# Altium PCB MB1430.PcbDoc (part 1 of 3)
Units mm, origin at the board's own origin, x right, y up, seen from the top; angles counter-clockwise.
Board outline 18.54 x 50.29 mm, 4 copper layers (Top Layer, Signal Layer 1, Signal Layer 2, Bottom Layer), stack 1.614 mm thick; 124 components, 85 nets, 561 pads, 241 vias.
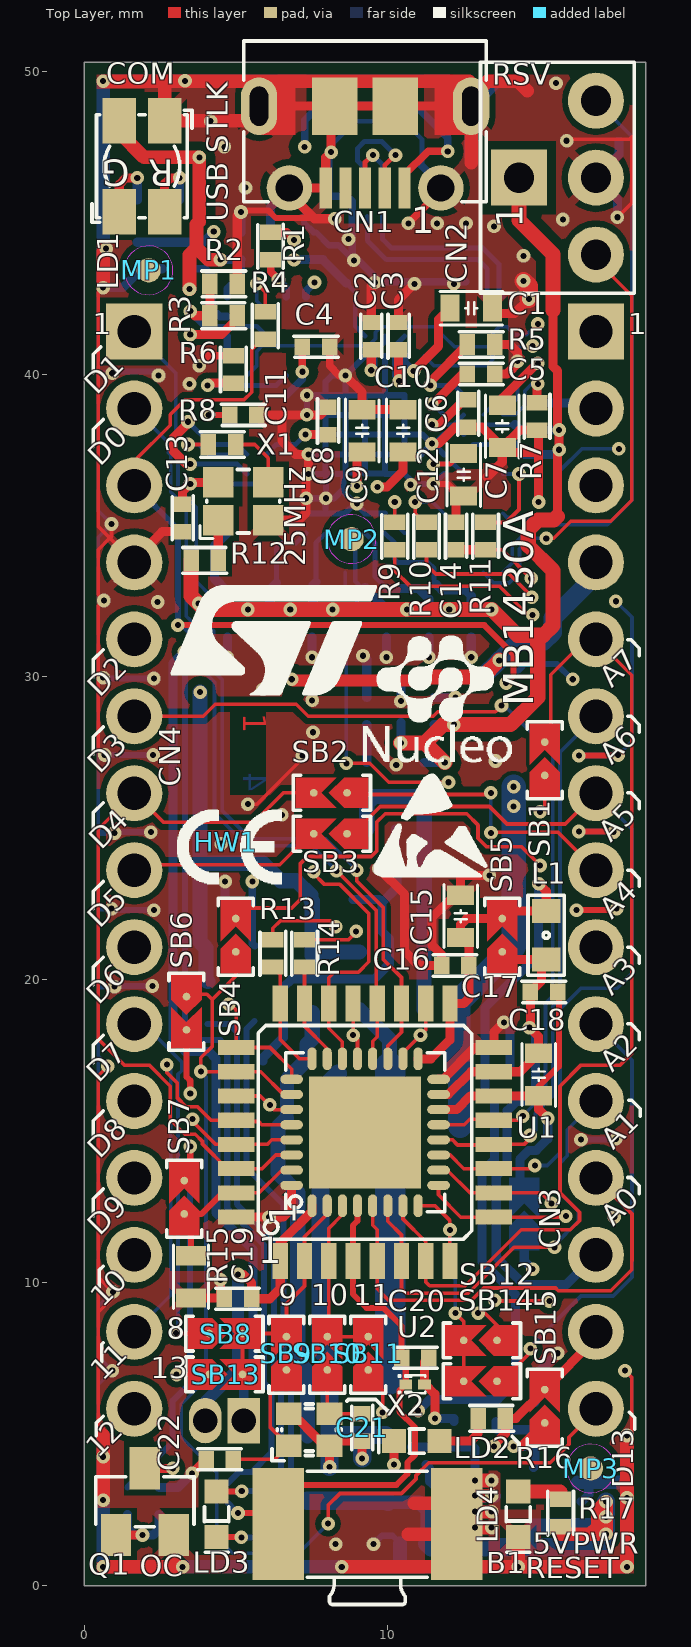
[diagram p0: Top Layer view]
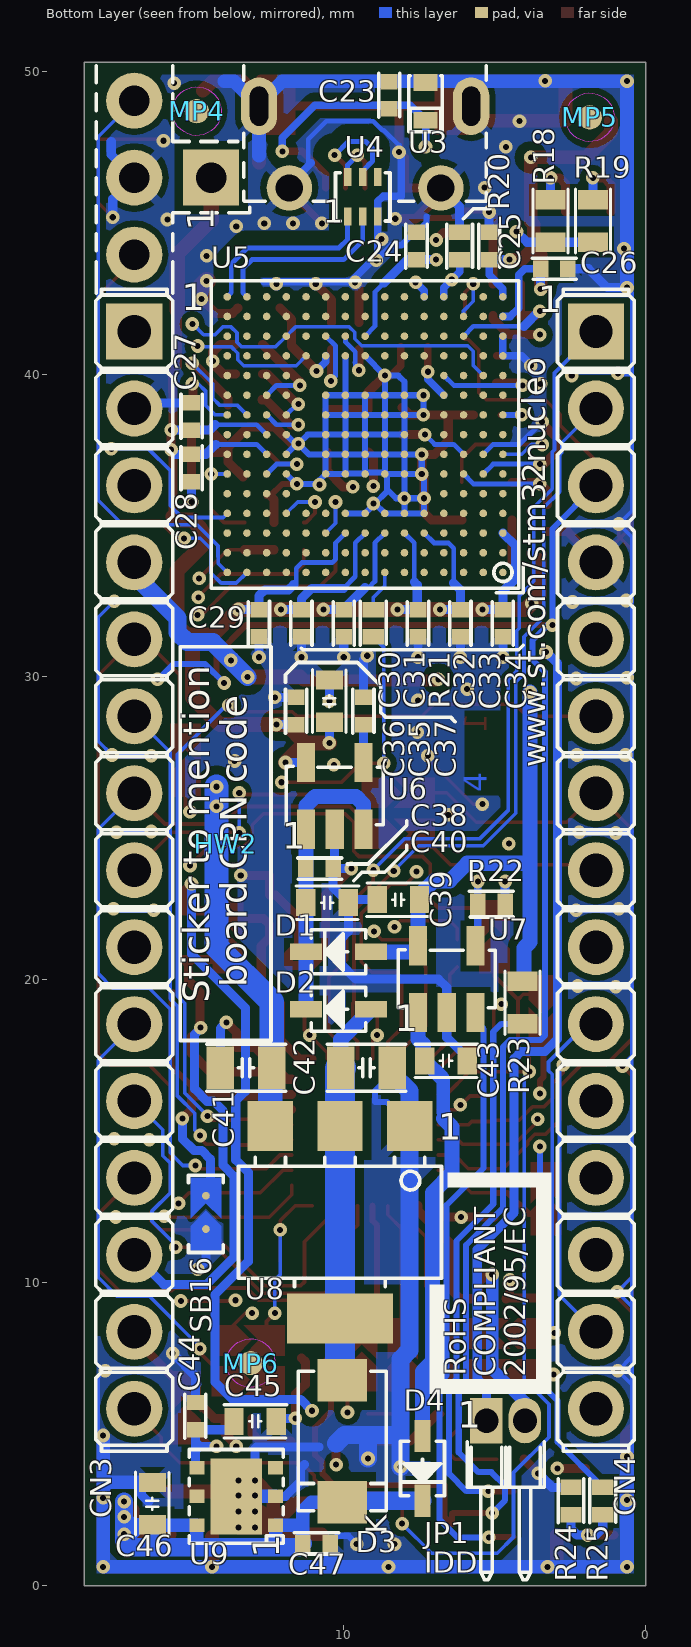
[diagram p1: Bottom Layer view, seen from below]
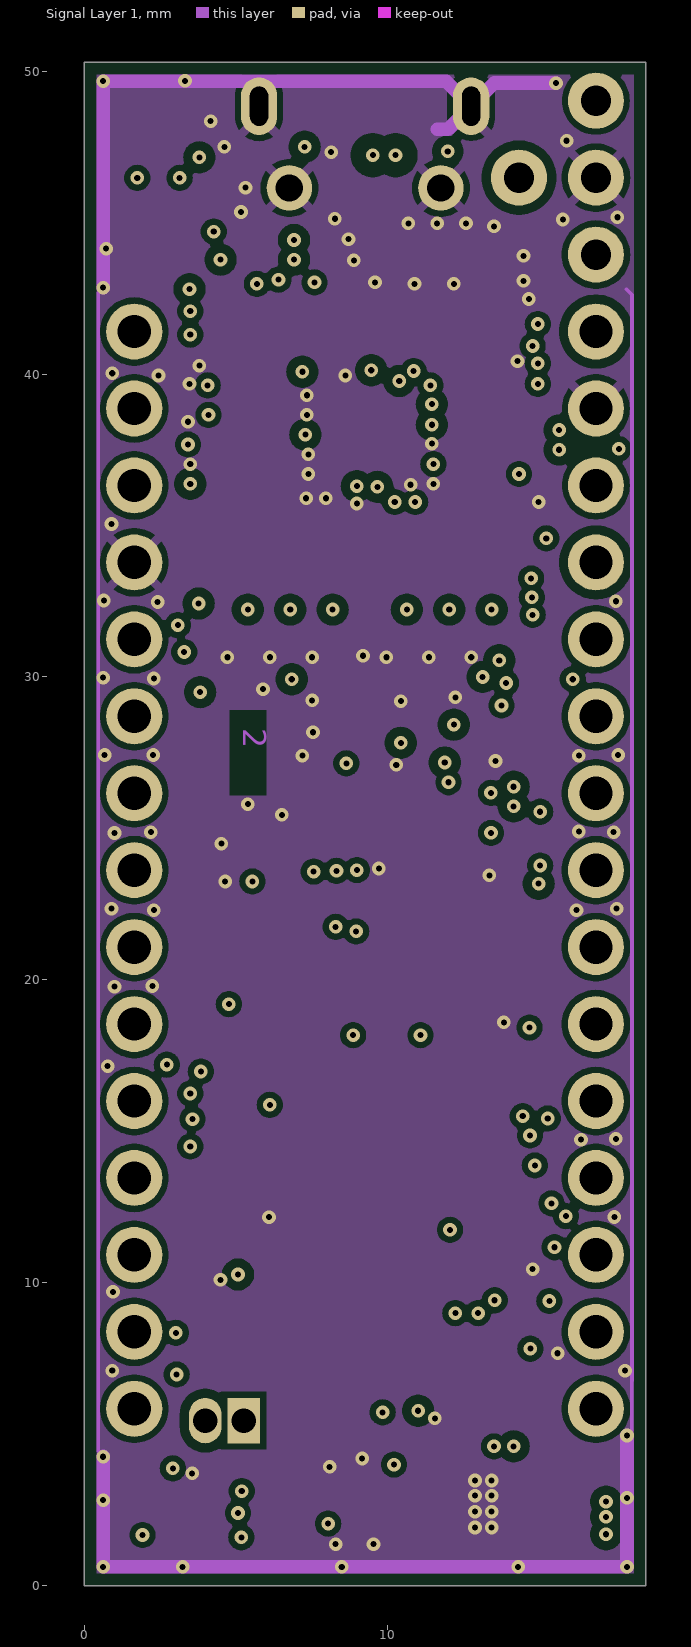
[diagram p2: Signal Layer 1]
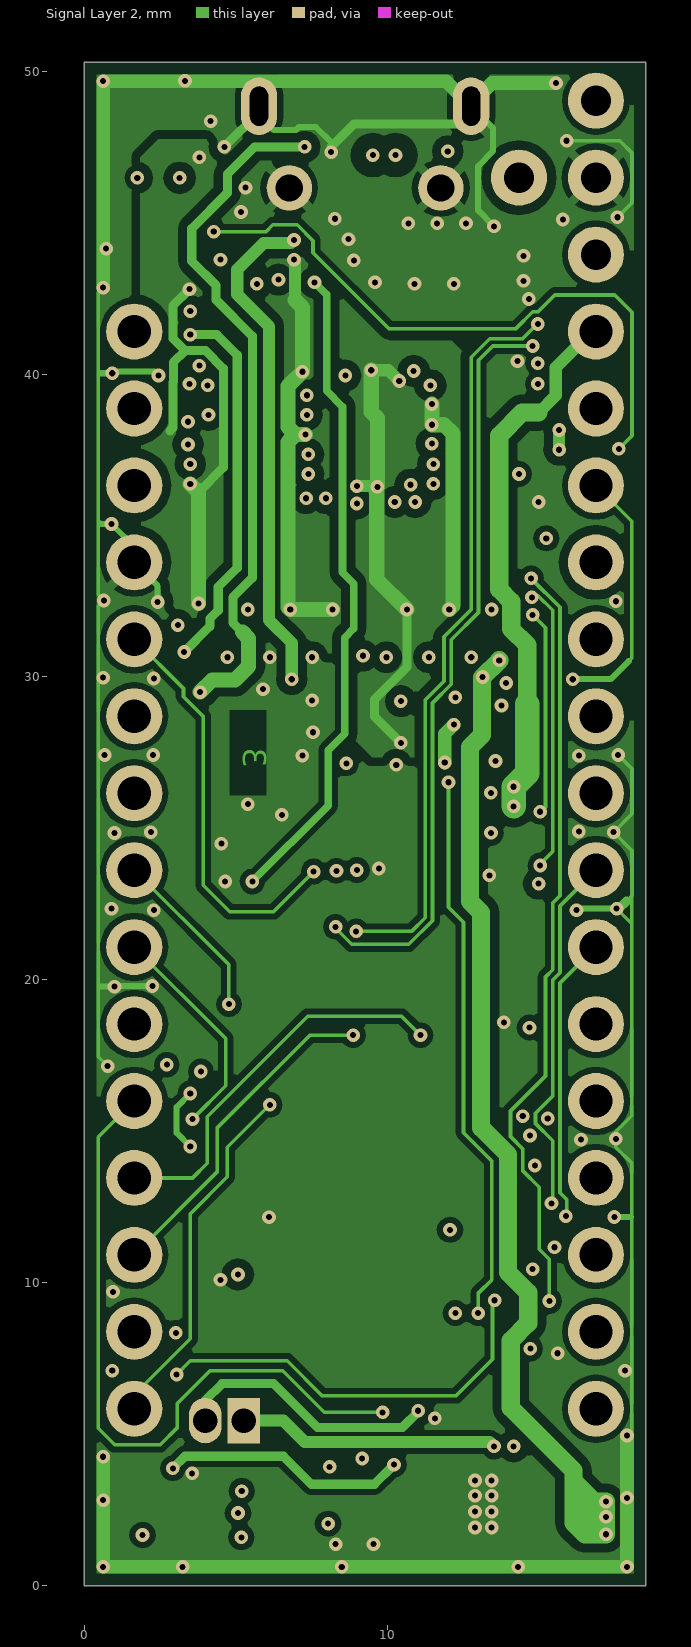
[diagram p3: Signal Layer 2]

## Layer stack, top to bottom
Top Solder: solder mask 0.015, Solder Resist, Dk 3.5
Top Layer: signal copper 0.042
Dielectric 1: prepreg 0.106, PP-IT-180A, Dk 4.2
Signal Layer 1: signal copper 0.035
Dielectric 2: core 1.248, FR4, Dk 4.2
Signal Layer 2: signal copper 0.035
Dielectric 3: prepreg 0.106, PP-IT-180A, Dk 4.2
Bottom Layer: signal copper 0.042
Bottom Solder: solder mask 0.015, Solder Resist, Dk 3.5

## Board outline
0,0 0,50.292 18.542,50.292 18.542,0

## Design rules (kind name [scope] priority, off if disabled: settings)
BoardOutlineClearance [All] p1: gap=0.4 ignorepadtopadclearanceinfootprint=FALSE
Clearance Clearance_USB [InNetClass('USB')] p1: gap=0.12 ignorepadtopadclearanceinfootprint=TRUE except(0.2: Arc-THPad Arc-Fill Track-THPad Track-Fill SMDPad-SMDPad SMDPad-THPad SMDPad-Fill THPad-THPad THPad-Fill Via-Fill Fill-Fill; 0.5: Arc-Poly Track-Poly SMDPad-Poly THPad-Poly Via-Poly Fill-Poly Poly-Poly)
Clearance Clearance_ALIMS [InNetClass('ALIMS')] p2: gap=0.12 ignorepadtopadclearanceinfootprint=TRUE except(0.2: Arc-THPad Arc-Fill Track-THPad Track-Fill SMDPad-SMDPad SMDPad-THPad SMDPad-Fill THPad-THPad THPad-Fill Via-Fill Fill-Fill; 0.3: Arc-Poly Track-Poly SMDPad-Poly THPad-Poly Via-Poly Fill-Poly Poly-Poly)
Clearance [All] p3: gap=0.12 ignorepadtopadclearanceinfootprint=TRUE except(0.2: Arc-THPad Arc-Fill Arc-Poly Track-THPad Track-Fill Track-Poly SMDPad-SMDPad SMDPad-THPad SMDPad-Fill SMDPad-Poly THPad-THPad THPad-Fill THPad-Poly Via-Fill Via-Poly Fill-Fill Fill-Poly Poly-Poly)
ComponentClearance [All] p1 off: gap=0.025 collisioncheckmode=3 verticalgap=2540 showdistances=TRUE
DiffPairsRouting DiffPairsRouting_USB [InDifferentialPairClass('DIFF_USB')] p1: maxlimit=0.226 minlimit=0.226 mostfreqgap=0.226 toplayer_minwidth=0.16 toplayer_maxwidth=0.16 toplayer_prefwidth=0.16 midlayer1_minwidth=0.16 midlayer1_maxwidth=0.16 midlayer1_prefwidth=0.16 midlayer2_minwidth=0.16 midlayer2_maxwidth=0.16 midlayer2_prefwidth=0.16 bottomlayer_minwidth=0.16 bottomlayer_maxwidth=0.16 bottomlayer_prefwidth=0.16 maxuncoupledlength=50
FanoutControl Fanout_BGA [IsBGA] p1: bgadir=Out bgaviamode=Closest fanoutstyle=Auto fanoutdirection=Alternating viagrid=0.025 // Fanout_BGA (Default Rule)
FanoutControl Fanout_LCC [IsLCC] p2: bgadir=Out bgaviamode=Closest fanoutstyle=Auto fanoutdirection=Alternating viagrid=0.025 // Fanout_LCC (Default Rule)
FanoutControl Fanout_SOIC [IsSOIC] p3: bgadir=Out bgaviamode=Closest fanoutstyle=Auto fanoutdirection=Alternating viagrid=0.025 // Fanout_SOIC (Default Rule)
FanoutControl Fanout_Small [(CompPinCount < 5)] p4: bgadir=Out bgaviamode=Closest fanoutstyle=Auto fanoutdirection=OutThenIn viagrid=0.025 // Fanout_Small (Default Rule)
FanoutControl Fanout_Default [All] p5: bgadir=Out bgaviamode=Closest fanoutstyle=Auto fanoutdirection=Alternating viagrid=0.025 // Fanout_Default (Default Rule)
Height [All] p1 off: minheight=0 maxheight=100 prefheight=0.5
HoleSize [All] p1: absolutevalues=TRUE maxlimit=10 minlimit=0.15 maxpercent=80.000 minpercent=20.000
HoleToHoleClearance [All] p1: gap=0.25 allowstackedmicrovias=TRUE
Length Length_USB [InNetClass('USB')] p1: maxlimit=50 minlimit=1
MatchedLengths [InDifferentialPairClass('DIFF_USB')] p1: tolerance=0.2 checknetsindiffpair=TRUE checkdiffpairvsdiffpair=FALSE checkxsignals=FALSE checkothers=FALSE
MinimumSolderMaskSliver [All] p1: minsoldermaskwidth=0
PlaneClearance [All] p1: clearance=0.6
PolygonConnect PolygonConnect__DEFAULT [All] p1: thpad.connectstyle=Relief thpad.reliefconductorwidth=0.3 thpad.reliefentries=4 thpad.polygonreliefangle="45 Angle" thpad.airgapwidth=0.2 smdpad.connectstyle=Relief smdpad.reliefconductorwidth=0.3 smdpad.reliefentries=4 smdpad.polygonreliefangle="45 Angle" smdpad.airgapwidth=0.2 via.connectstyle=Direct via.reliefconductorwidth=0.254 via.reliefentries=4 via.polygonreliefangle="45 Angle" via.airgapwidth=0.254
RoutingVias [All] p1: holewidth=0.2 width=0.45 viastyle="Through Hole" minholewidth=0.2 minwidth=0.45 maxholewidth=0.2 maxwidth=0.45
SilkToSilkClearance [All] p1: silktosilkclearance=0
SilkToSolderMaskClearance [IsPad] p1: minsilkscreentomaskgap=0 clearancetoexposedcopper=TRUE
SolderMaskExpansion [All] p1: expansion=0.05
Width Width_ALIMS [InNetClass('ALIMS')] p1: maxlimit=10 minlimit=0.12 preferedwidth=0.3
Width Width_GND [InNetClass('GND')] p2: maxlimit=10 minlimit=0.12 preferedwidth=0.3 minimp=50.000000 maximp=50.000000 favimp=50.000000
Width [All] p3: maxlimit=10 minlimit=0.12 preferedwidth=0.12
16 further rules are at their usual default settings.

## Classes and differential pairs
net class USB: USB_DEV_HS_CN_N USB_DEV_HS_CN_P USB_DEV_HS_N USB_DEV_HS_P
net class GND: AGND AVDD GND GNDDetect
net class ALIMS: 3V3_STLK 5V 5V_USB_CHGR 5V_USB_STLK 5V_VIN NetC44_2 VDD VIN
differential pair class DIFF_USB: USB_DEV_HS USB_DEV_HS_CN
differential pair USB_DEV_HS_CN: +USB_DEV_HS_CN_P -USB_DEV_HS_CN_N
differential pair USB_DEV_HS: +USB_DEV_HS_P -USB_DEV_HS_N

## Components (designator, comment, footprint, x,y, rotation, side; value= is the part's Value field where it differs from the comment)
B1 "" SWI_C&K_ITT_KSS221G 9.347,2.032 r0 top locked value=KSS221GLFS
C1 "" C0603 12.775,42.175 r180 top value=2.2uF
C2 "" C0402 9.475,41.25 r270 top value=100nF
C3 "" C0402 10.375,41.25 r270 top value=100nF
C4 "" C0402 7.65,40.9 r180 top value=100nF
C5 "" C0402 13.1,40 r180 top value=100nF
C6 "" C0402 12.675,38.7 r90 top value=100nF
C7 "" C0603 13.8,38.275 r90 top value=2.2uF
C8 "" C0402 8.05,38.45 r270 top value=100nF
C9 "" C0603 9.175,38.125 r270 top value=4.7uF
C10 "" C0603 10.525,38.125 r270 top value=1uF
C11 "" C0402 5.25,38.65 r180 top value=100nF
C12 "" C0603 12.525,36.675 r90 top value=2.2uF
C13 "" C0402 3.25,35.25 r90 top value=100nF
C14 "" C0402 12.275,34.65 r270 top value=20pF
C15 "" C0603 12.425,22.1 r270 top value=4.7uF
C16 "" C0402 12.25,20.475 r0 top value=100nF
C17 "" C0402 15.175,19.6 r180 top value=100nF
C18 "" C0603 15,16.875 r90 top value=1uF
C19 "" C0402 5.075,9.475 r0 top value=100nF
C20 "" C0402 10.925,7.525 r180 top value=100nF
C21 "" C0402 9.175,5.225 r90 top value=6.8pF
C22 "" C0402 4.475,4.175 r0 top value=6.8pF
C23 "" C0402 8.475,49.2 r270 bottom value=100pF
C24 "" C0402 7.575,44.225 r270 bottom value=100nF
C25 "" C0402 5.175,44.225 r270 bottom value=100nF
C26 "" C0402 3.025,43.475 r0 bottom value=100nF
C27 "" C0402 15,38.6 r270 bottom value=100nF
C28 "" C0402 15,36.9 r90 bottom value=100nF
C29 "" C0402 12.775,31.775 r90 bottom value=100nF
C30 "" C0402 11.375,31.775 r90 bottom value=100nF
C31 "" C0402 9.975,31.775 r90 bottom value=100nF
C32 "" C0402 7.525,31.775 r90 bottom value=100nF
C33 "" C0402 6.125,31.775 r90 bottom value=100nF
C34 "" C0402 4.725,31.775 r90 bottom value=100nF
C35 "" C0603 10.45,29.2 r270 bottom value=1uF
C36 "" C0402 11.55,28.875 r270 bottom value=100nF
C37 "" C0402 9.325,28.875 r270 bottom value=10nF
C38 "" C0402 10.775,23.675 r0 bottom value=100nF
C39 "" C0603 8.175,22.65 r180 bottom value=1uF
C40 "" C0603 10.525,22.55 r0 bottom value=1uF
C41 "" C0805 13.2,17.1 r180 bottom value=10uF
C42 "" C0805 9.225,17.1 r0 bottom value=10uF
C43 "" C0603 6.6,17.325 r0 bottom value=1uF
C44 "" C0402 14.875,5.6 r270 bottom value=100nF
C45 "" C0603 12.9,5.425 r0 bottom value=1uF
C46 "" C0603 16.292,2.708 r270 bottom value=1uF
C47 "" C0402 10.875,1.4 r0 bottom value=100nF
CART1 "Comment" Sheetbox_4L2S -36.495,-22.202 r0 top
CN1 "" CON_USBMICROB_MOLEX_105017-0001_H2P90 9.271,50.292 r180 top locked value=USB_uB_105017-0001
CN2 "" CON_SAMTEC_TSW-103-07-X-D_CUSTOM_4PINS__V1-3 15.621,46.482 r270 top value="SWD connector 2.54pitch 1+3 pins"
CN3 "" CON_LYCN_313115S161145 16.891,23.622 r270 bottom value="Header 15X1"
CN4 "" CON_LYCN_313115S161145 1.651,23.622 r270 bottom value="Header 15X1"
D1 "" DIO_SOD323 10.15,20.925 r0 bottom value=BAT60JFILM
D2 "" DIO_SOD323 10.15,19.025 r0 bottom value=BAT60JFILM
D3 "" DIO_SMA_1A_2K 10.025,4.775 r90 bottom value=STPS1L30A
D4 "" DIO_SOD323 7.375,3.875 r270 bottom value=BAT60JFILM
HW1 "" LOGO_CE 4.675,24.55 r0 top value="LOGO CE"
HW2 "Comment" STICKER_BOARD-CPN_13X3 13.875,24.5 r90 bottom
JP1 "" CON_WP_707-2-02-2-20-00 4.63,5.45 r180 bottom locked value="Shunt Fitted"
L1 "" L0603 15.25,21.475 r90 top value=600R@100MHz
LD1 "" LED_BI-GR_HSMF-A201-A00J1 1.905,46.863 r180 top locked value=LD_BICOLOR_CMS
LD2 "" LED_0603_GREEN 10.975,4.775 r180 top value=GREEN
LD3 "LED_red" LED_0603_RED_H0P4 4.369,2.362 r270 top locked value=RED
LD4 "LED_green" LED_0603_GREEN 14.326,2.362 r270 top locked value=GREEN
MP1 "Comment" MIRE_PLACE_SMD_0P8MM 2.125,43.425 r0 top
MP2 "Comment" MIRE_PLACE_SMD_0P8MM 8.825,34.55 r0 top
MP3 "Comment" MIRE_PLACE_SMD_0P8MM 16.725,3.875 r0 top
MP4 "Comment" MIRE_PLACE_SMD_0P8MM 14.825,48.675 r180 bottom
MP5 "Comment" MIRE_PLACE_SMD_0P8MM 1.85,48.475 r180 bottom
MP6 "Comment" MIRE_PLACE_SMD_0P8MM 13.05,7.35 r180 bottom
Q1 "" NPN_SOT23 2,2.775 r0 top value=9013-SOT23
R1 "" R0402 6.15,44.225 r90 top value=2K7
R2 "" R0402 4.6,42.975 r180 top value=4K7
R3 "" R0402 4.6,41.925 r0 top value=4K7
R4 "" R0402 5.975,41.6 r90 top value=22R
R5 "" R0402 13.1,40.975 r180 top value=100R
R6 "" R0402 4.925,40.15 r270 top value=10K
R7 "" R0402 14.95,38.6 r90 top value=3K
R8 "" R0402 4.55,37.675 r180 top value=100R
R9 "" R0402 10.25,34.65 r90 top value=22R
R10 "" R0402 11.3,34.65 r90 top value=22R
R11 "" R0402 13.25,34.65 r270 top value=100R
R12 "" R0402 3.975,33.85 r0 top value=10K
R13 "" R0402 6.225,20.875 r90 top value=22R
R14 "" R0402 7.275,20.875 r90 top value=22R
R15 "" R0603 3.525,10.2 r90 top value=10K
R16 "Resistor" R0402 13.45,5.525 r0 top value=270R
R17 "" R0402 15.725,2.4 r270 top value=620R
R18 "" R0603 3.15,45.05 r270 bottom value=330R
R19 "" R0603 1.75,45.05 r270 bottom value=330R
R20 "" R0402 6.15,44.225 r270 bottom value=4K7
R21 "" R0402 9,31.775 r270 bottom value=22R
R22 "" R0402 5.1,22.5 r0 bottom value=10K
R23 "" R0603 4.075,19.25 r270 bottom value=1K
R24 "Resistor" R0402 2.475,2.8 r270 bottom value=100K
R25 "Resistor" R0402 1.425,2.8 r270 bottom value=47K
SB1 "" SOLDER-BRIDGE_R0603-0R 15.2,27.25 r90 top
SB2 "" SOLDER-BRIDGE_R0603-0R 8.175,26.175 r180 top
SB3 "" SOLDER-BRIDGE_R0603-0R 8.175,24.825 r180 top
SB4 "" SOLDER-BRIDGE_R0603-0R 5,21.425 r90 top
SB5 "" SOLDER-BRIDGE_R0603-0R 13.8,21.425 r90 top
SB6 "" SOLDER-BRIDGE_R0603-0R 3.375,18.95 r270 top
SB7 "" SOLDER-BRIDGE_R0603-0R 3.3,12.775 r90 top
SB8 "" SOLDER-BRIDGE_R0603-0R 4.625,8.325 r0 top
SB9 "" SOLDER-BRIDGE_R0603-0R 6.675,7.625 r90 top
SB10 "" SOLDER-BRIDGE_R0603-0R 8.025,7.625 r90 top
SB11 "" SOLDER-BRIDGE_R0603-0R 9.375,7.625 r90 top
SB12 "" SOLDER-BRIDGE_R0603-0R 13.125,8.1 r180 top
SB13 "" SOLDER-BRIDGE_R0603-0R 4.625,6.975 r0 top
SB14 "" SOLDER-BRIDGE_R0603-0R 13.125,6.75 r180 top
SB15 "" SOLDER-BRIDGE_R0603-0R 15.2,5.875 r90 top
SB16 "" SOLDER-BRIDGE_R0603-0R 14.525,12.275 r90 bottom
U1 "" ICC_LQFP32_7X7_P080__UFQFPN32-EPAD_5X5_P050__DI 9.271,14.969 r0 top value=STM32G431KBT6
U2 "" ESD_ST0201 10.925,6.65 r0 top value=ESDALC6V1-1U2
U3 "" ESD_QFN2_1P6X1_P125 7.275,49 r90 bottom value=ESDA7P60-1U1M
U4 "" ESD_QFN-6L_1P7X1P5_P050 9.35,45.85 r180 bottom value=ECMF02-2AMX6
U5 "" ICC_UFBGA201_176+25_10X10_P065 9.271,38 r0 bottom value=ST-LINKV3E_SWD
U6 "" REG_SOT23-5L 10.275,26.075 r180 bottom value=LD3985M33R
U7 "" MOS_SOT23-5L 6.575,20.025 r180 bottom value=STMPS2151STR
U8 "" REG_SOT223-TAB 10.1,12 r0 bottom value=LD1117S50TR
U9 "" ICC_DFN6-EPAD_3X3_P095 13.525,2.95 r90 bottom value=LD39050PU33R
X1 "" OSC_NDK_NZ2520SB_4P 5.25,35.8 r0 top value=25MHz
X2 "" CRY_NX2016SA_4P 7.425,5.15 r0 top value=24MHz

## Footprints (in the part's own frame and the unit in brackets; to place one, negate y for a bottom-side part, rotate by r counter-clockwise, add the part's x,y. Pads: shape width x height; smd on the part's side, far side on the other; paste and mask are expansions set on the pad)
C0402 [mm]
  rect 0.51x0.56 smd mask+0.05: 1(-0.45,0) 2(0.45,0)
  silkscreen extent -0.72,-0.35 0.72,0.35, body extent -0.5,-0.3 0.5,0.3, height 0.4
C0603 [mm]
  rect 0.64x0.89 smd mask+0.05: 1(-0.7,0) 2(0.7,0)
  silkscreen extent -1.05,-0.55 1.02,0.55, body extent -0.9,-0.5 0.9,0.5, height 1.4
C0805 [mm]
  rect 0.9x1.4 smd mask+0.05: 1(-0.85,0) 2(0.85,0)
  silkscreen extent -1.3,-0.77 1.3,0.77, body extent -1.1,-0.7 1.1,0.7, height 1.35
CON_LYCN_313115S161145 [mm]
  rect 1.85x1.85 / inner round 1.85 / far side rect 1.85x1.85 hole 1.1 mask+0.05: 1(-17.78,0)
  round 1.85 hole 1.1 mask+0.05: 2(-15.24,0) 3(-12.7,0) 4(-10.16,0) 5(-7.62,0) 6(-5.08,0) 7(-2.54,0) 8(0,0) 9(2.54,0) 10(5.08,0) 11(7.62,0) 12(10.16,0) 13(12.7,0) 14(15.24,0) 15(17.78,0)
  silkscreen extent -19.18,-1.27 19.18,1.27, body extent -19.18,-1.27 19.18,1.27, height 8.5
CON_SAMTEC_TSW-103-07-X-D_CUSTOM_4PINS__V1-3 [mm] "MCD-01430"
  rect 1.85x1.85 / inner round 1.85 / far side rect 1.85x1.85 hole 1 mask+0.05: 1(0,-1.27)
  round 1.85 hole 1 mask+0.05: 2(-2.54,1.27) 3(0,1.27) 4(2.54,1.27)
  silkscreen extent -3.81,-2.54 3.81,2.54, body extent -3.81,-2.54 3.81,2.54, height 8.38
CON_USBMICROB_MOLEX_105017-0001_H2P90 [mm]
  rect 0.4x1.35 smd mask+0.05: 1(-1.3,4.15) 2(-0.65,4.15) 3(0,4.15) 4(0.65,4.15) 5(1.3,4.15)
  round 1.5 hole 0.9 mask+0.05: 6(-2.5,4.15) 7(2.5,4.15)
  oval 1.2x1.9 hole 0.6 slot 1.3 at 90 deg mask+0.05: 8(3.5,1.45) 9(-3.5,1.45)
  rect 1.5x1.9 smd mask+0.05: 10(-1,1.45) 11(1,1.45)
  Top Layer region: -3.5,2.4 -2.3,2.4 -2.3,0.5 -3.5,0.5 -3.5,2.4
  Top Layer region: 2.3,2.4 3.5,2.4 3.5,0.5 2.3,0.5 2.3,2.4
  silkscreen extent -4,-0.7 4,4.6, body extent -4.1,-1.15 4.1,4.66, height 2.9
CON_WP_707-2-02-2-20-00 [mm]
  rect 1.07x1.5 hole 0.8 mask+0.05: 1(-0.635,0)
  oval 1.07x1.5 hole 0.8 mask+0.05: 2(0.635,0)
  silkscreen extent -1.27,-5.25 1.27,-0.7, body extent -1.27,-5.25 1.27,0.2, height 2.1
CRY_NX2016SA_4P [mm]
  rect 0.85x0.75 smd mask+0.05: 1(-0.675,-0.525) 2(0.675,-0.525) 3(0.675,0.525) 4(-0.675,0.525)
  silkscreen extent -1.22,-1.02 1.05,0.85, body extent -1.05,-0.85 1.05,0.85, height 0.7
DIO_SMA_1A_2K [mm]
  rect 1.4x1.64 smd mask+0.05: 1(2.015,0) 2(-2.015,0)
  silkscreen extent -2.3,-1.45 2.3,1.45, body extent -2.75,-1.45 2.75,1.45, height 2.7
DIO_SOD323 [mm]
  rect 1.06x0.54 smd mask+0.05: 1(-1.07,0) 2(1.07,0)
  silkscreen extent -0.9,-0.72 0.9,0.72, body extent -1.3,-0.78 1.3,0.78, height 1.17
ESD_QFN2_1P6X1_P125 [mm]
  rect 0.55x0.8 smd mask+0.05: 1(-0.625,0) 2(0.625,0)
  silkscreen extent -1,-0.55 0.85,0.55, body extent -0.85,-0.55 0.85,0.55, height 0.61
ESD_QFN-6L_1P7X1P5_P050 [mm]
  rect 0.25x0.6 smd mask+0.05: 1(-0.5,-0.65) 2(0,-0.65) 3(0.5,-0.65) 4(0.5,0.65) 5(0,0.65) 6(-0.5,0.65)
  silkscreen extent -0.9,-0.8 0.9,0.8, body extent -0.9,-0.8 0.9,0.8, height 0.56
ESD_ST0201 [mm]
  rect 0.425x0.33 smd mask+0.05: 1(-0.312,0) 2(0.312,0)
  silkscreen extent -0.55,-0.3 0.33,0.3, body extent -0.34,-0.18 0.34,0.18, height 0.34
ICC_DFN6-EPAD_3X3_P095 [mm]
  rect 0.45x0.5 smd mask+0.05: 1(-0.95,-1.3) 2(0,-1.3) 3(0.95,-1.3) 4(0.95,1.3) 5(0,1.3) 6(-0.95,1.3)
  rect 2.5x1.7 smd mask+0.05: EP(0,0)
  silkscreen extent -1.55,-1.55 1.55,1.55, body extent -1.55,-1.55 1.55,1.55, height 1
ICC_LQFP32_7X7_P080__UFQFPN32-EPAD_5X5_P050__DI [mm] "MCD-01396"
  rect 0.5x1.2 smd mask+0.05: 1(-2.8,-4.25) 2(-2,-4.25) 3(-1.2,-4.25) 4(-0.4,-4.25) 5(0.4,-4.25) 6(1.2,-4.25) 7(2,-4.25) 8(2.8,-4.25) 17(2.8,4.25) 18(2,4.25) 19(1.2,4.25) 20(0.4,4.25) 21(-0.4,4.25) 22(-1.2,4.25) 23(-2,4.25) 24(-2.8,4.25)
  oval 0.3x0.75 smd mask+0.05: 1(-1.75,-2.425) 2(-1.25,-2.425) 3(-0.75,-2.425) 4(-0.25,-2.425) 5(0.25,-2.425) 6(0.75,-2.425) 7(1.25,-2.425) 8(1.75,-2.425) 17(1.75,2.425) 18(1.25,2.425) 19(0.75,2.425) 20(0.25,2.425) 21(-0.25,2.425) 22(-0.75,2.425) 23(-1.25,2.425) 24(-1.75,2.425)
  oval 0.75x0.3 smd mask+0.05: 9(2.425,-1.75) 10(2.425,-1.25) 11(2.425,-0.75) 12(2.425,-0.25) 13(2.425,0.25) 14(2.425,0.75) 15(2.425,1.25) 16(2.425,1.75) 25(-2.425,1.75) 26(-2.425,1.25) 27(-2.425,0.75) 28(-2.425,0.25) 29(-2.425,-0.25) 30(-2.425,-0.75) 31(-2.425,-1.25) 32(-2.425,-1.75)
  rect 1.2x0.5 smd mask+0.05: 9(4.25,-2.8) 10(4.25,-2) 11(4.25,-1.2) 12(4.25,-0.4) 13(4.25,0.4) 14(4.25,1.2) 15(4.25,2) 16(4.25,2.8) 25(-4.25,2.8) 26(-4.25,2) 27(-4.25,1.2) 28(-4.25,0.4) 29(-4.25,-0.4) 30(-4.25,-1.2) 31(-4.25,-2) 32(-4.25,-2.8)
  rect 3.7x3.7 smd mask+0.05: 33(0,0)
  silkscreen extent -3.52,-3.52 3.52,3.52, body extent -4.5,-4.5 4.5,4.5, height 1.63
ICC_UFBGA201_176+25_10X10_P065 [mm] "IPC"
  round 0.25 smd mask+0.05: A1(-4.55,4.55) A2(-3.9,4.55) A3(-3.25,4.55) A4(-2.6,4.55) A5(-1.95,4.55) A6(-1.3,4.55) A7(-0.65,4.55) A8(0,4.55) A9(0.65,4.55) A10(1.3,4.55) A11(1.95,4.55) A12(2.6,4.55) A13(3.25,4.55) A14(3.9,4.55) A15(4.55,4.55) B1(-4.55,3.9) B2(-3.9,3.9) B3(-3.25,3.9) B4(-2.6,3.9) B5(-1.95,3.9) B6(-1.3,3.9) B7(-0.65,3.9) B8(0,3.9) B9(0.65,3.9) B10(1.3,3.9) B11(1.95,3.9) B12(2.6,3.9) B13(3.25,3.9) B14(3.9,3.9) B15(4.55,3.9) C1(-4.55,3.25) C2(-3.9,3.25) C3(-3.25,3.25) C4(-2.6,3.25) C5(-1.95,3.25) C6(-1.3,3.25) C7(-0.65,3.25) C8(0,3.25) C9(0.65,3.25) C10(1.3,3.25) C11(1.95,3.25) C12(2.6,3.25) C13(3.25,3.25) C14(3.9,3.25) C15(4.55,3.25) D1(-4.55,2.6) D2(-3.9,2.6) D3(-3.25,2.6) D4(-2.6,2.6) D5(-1.95,2.6) D6(-1.3,2.6) D7(-0.65,2.6) D8(0,2.6) D9(0.65,2.6) D10(1.3,2.6) D11(1.95,2.6) D12(2.6,2.6) D13(3.25,2.6) D14(3.9,2.6) D15(4.55,2.6) E1(-4.55,1.95) E2(-3.9,1.95) E3(-3.25,1.95) E4(-2.6,1.95) E12(2.6,1.95) E13(3.25,1.95) E14(3.9,1.95) E15(4.55,1.95) F1(-4.55,1.3) F2(-3.9,1.3) F3(-3.25,1.3) F4(-2.6,1.3) F6(-1.3,1.3) F7(-0.65,1.3) F8(0,1.3) F9(0.65,1.3) F10(1.3,1.3) F12(2.6,1.3) F13(3.25,1.3) F14(3.9,1.3) F15(4.55,1.3) G1(-4.55,0.65) G2(-3.9,0.65) G3(-3.25,0.65) G4(-2.6,0.65) G6(-1.3,0.65) G7(-0.65,0.65) G8(0,0.65) G9(0.65,0.65) G10(1.3,0.65) G12(2.6,0.65) G13(3.25,0.65) G14(3.9,0.65) G15(4.55,0.65) H1(-4.55,0) H2(-3.9,0) H3(-3.25,0) H4(-2.6,0) H6(-1.3,0) H7(-0.65,0) H8(0,0) H9(0.65,0) H10(1.3,0) H12(2.6,0) H13(3.25,0) H14(3.9,0) H15(4.55,0) J1(-4.55,-0.65) J2(-3.9,-0.65) J3(-3.25,-0.65) J4(-2.6,-0.65) J6(-1.3,-0.65) J7(-0.65,-0.65) J8(0,-0.65) J9(0.65,-0.65) J10(1.3,-0.65) J12(2.6,-0.65) J13(3.25,-0.65) J14(3.9,-0.65) J15(4.55,-0.65) K1(-4.55,-1.3) K2(-3.9,-1.3) K3(-3.25,-1.3) K4(-2.6,-1.3) K6(-1.3,-1.3) K7(-0.65,-1.3) K8(0,-1.3) K9(0.65,-1.3) K10(1.3,-1.3) K12(2.6,-1.3) K13(3.25,-1.3) K14(3.9,-1.3) K15(4.55,-1.3) L1(-4.55,-1.95) L2(-3.9,-1.95) L3(-3.25,-1.95) L4(-2.6,-1.95) L12(2.6,-1.95) L13(3.25,-1.95) L14(3.9,-1.95) L15(4.55,-1.95) M1(-4.55,-2.6) M2(-3.9,-2.6) M3(-3.25,-2.6) M4(-2.6,-2.6) M5(-1.95,-2.6) M6(-1.3,-2.6) M7(-0.65,-2.6) M8(0,-2.6) M9(0.65,-2.6) M10(1.3,-2.6) M11(1.95,-2.6) M12(2.6,-2.6) M13(3.25,-2.6) M14(3.9,-2.6) M15(4.55,-2.6) N1(-4.55,-3.25) N2(-3.9,-3.25) N3(-3.25,-3.25) N4(-2.6,-3.25) N5(-1.95,-3.25) N6(-1.3,-3.25) N7(-0.65,-3.25) N8(0,-3.25) N9(0.65,-3.25) N10(1.3,-3.25) N11(1.95,-3.25) N12(2.6,-3.25) N13(3.25,-3.25) N14(3.9,-3.25) N15(4.55,-3.25) P1(-4.55,-3.9) P2(-3.9,-3.9) P3(-3.25,-3.9) P4(-2.6,-3.9) P5(-1.95,-3.9) P6(-1.3,-3.9) P7(-0.65,-3.9) P8(0,-3.9) P9(0.65,-3.9) P10(1.3,-3.9) P11(1.95,-3.9) P12(2.6,-3.9) P13(3.25,-3.9) P14(3.9,-3.9) P15(4.55,-3.9) R1(-4.55,-4.55) R2(-3.9,-4.55) R3(-3.25,-4.55) R4(-2.6,-4.55) R5(-1.95,-4.55) R6(-1.3,-4.55) R7(-0.65,-4.55) R8(0,-4.55) R9(0.65,-4.55) R10(1.3,-4.55) R11(1.95,-4.55) R12(2.6,-4.55) R13(3.25,-4.55) R14(3.9,-4.55) R15(4.55,-4.55)
  silkscreen extent -5.22,-5.07 5.07,5.23, body extent -5.07,-5.07 5.07,5.07, height 0.61
L0603 [mm]
  rect 0.8x0.95 smd mask+0.05: 1(-0.8,0) 2(0.8,0)
  silkscreen extent -1.33,-0.6 1.33,0.6, body extent -0.87,-0.47 0.87,0.47, height 0.95
LED_0603_GREEN [mm]
  rect 0.8x0.8 smd mask+0.05: 1(-0.75,0) 2(0.75,0)
  silkscreen extent -0.25,-0.4 1.25,0.4, body extent -0.8,-0.4 0.8,0.4, height 0.6
LED_0603_RED_H0P4 [mm]
  rect 0.8x0.8 smd mask+0.05: 1(-0.75,0) 2(0.75,0)
  silkscreen extent -0.25,-0.4 1.25,0.4, body extent -0.8,-0.4 0.79,0.4, height 0.4
LED_BI-GR_HSMF-A201-A00J1 [mm]
  rect 1.1x1.5 smd mask+0.05: 1(-0.75,-1.5) 2(-0.75,1.5) 3(0.75,1.5) 4(0.75,-1.5)
  silkscreen extent -1.65,-1.85 1.65,1.85, body extent -1.5,-1.85 1.5,1.85, height 2.1
LOGO_CE [mm]
  silkscreen extent -1.61,-1.37 1.85,1.07
MIRE_PLACE_SMD_0P8MM [mm]
  round 0.8 smd paste-10 mask+0.2: 1(0,0)
  Top Layer keep-out circle w0.01: c0,0 r0.804
MOS_SOT23-5L [mm]
  rect 0.6x1.3 smd mask+0.05: 1(-0.95,-1.1) 2(0,-1.1) 3(0.95,-1.1) 4(0.95,1.1) 5(-0.95,1.1)
  silkscreen extent -1.6,-0.95 1.6,0.97, body extent -1.52,-1.25 1.52,1.25, height 1.45
NPN_SOT23 [mm]
  rect 1x1.4 smd mask+0.05: 1(-0.95,-1.1) 2(0.95,-1.1) 3(0,1.1)
  silkscreen extent -1.63,-0.82 1.63,0.82, body extent -1.56,-1.25 1.56,1.25, height 1.1
OSC_NDK_NZ2520SB_4P [mm]
  rect 1x1 smd mask+0.05: 1(-0.825,-0.625) 2(0.825,-0.625) 3(0.825,0.625) 4(-0.825,0.625)
  silkscreen extent -1.43,-1.22 1.2,1.05, body extent -1.3,-1.05 1.3,1.05, height 0.91
R0402 [mm]
  rect 0.51x0.7 smd mask+0.05: 1(-0.45,0) 2(0.45,0)
  silkscreen extent -0.72,-0.43 0.72,0.43, body extent -0.52,-0.3 0.52,0.3, height 0.4
R0603 [mm]
  rect 0.64x1 smd mask+0.05: 1(-0.7,0) 2(0.7,0)
  silkscreen extent -1.05,-0.58 1.05,0.58, body extent -0.9,-0.5 0.9,0.5, height 0.56
REG_SOT23-5L [mm]
  rect 0.6x1.3 smd mask+0.05: 1(-0.95,-1.1) 2(0,-1.1) 3(0.95,-1.1) 4(0.95,1.1) 5(-0.95,1.1)
  silkscreen extent -1.6,-0.95 1.6,0.97, body extent -1.52,-1.25 1.52,1.25, height 1.1
REG_SOT223-TAB [mm]
  rect 1.5x1.65 smd mask+0.05: 1(-2.3,-3.175) 2(0,-3.175) 3(2.3,-3.175)
  rect 3.5x1.65 smd mask+0.05: 4(0,3.175)
  silkscreen extent -3.35,-2.15 3.35,2.12, body extent -3.35,-3.48 3.35,3.48, height 1.8
Sheetbox_4L2S [mil] "Sheetbox 4 layers / 2 silkscreens"
  round 20 on Mech16: 1(813.78,210.69) 1(2736.9,210.69)
SOLDER-BRIDGE_R0603-0R [mil]
  round 10 smd paste-393.7: 1(-19.68,0) 2(23.62,0)
  Top Layer region: -5.91,19.68 13.78,0 -5.91,-19.69 47.24,-19.69 47.24,19.68 -5.91,19.68
  Top Layer region: -47.24,-19.69 -47.24,19.68 -15.75,19.68 3.94,0 -15.75,-19.69 -47.24,-19.69
  silkscreen extent -50,-23 50,23, body extent -36,-20 36,20, height 22
STICKER_BOARD-CPN_13X3 [mm] "Sticker to mention board CPN code"
  silkscreen extent -6.5,-1.5 6.5,1.5, body extent -6.5,-1.5 6.5,1.5, height 0.01
SWI_C&K_ITT_KSS221G [mm] "MCD-01335"
  rect 1.7x3.7 smd mask+0.05: 1(-2.95,0) 2(2.95,0)
  silkscreen extent -1.97,-2.65 1.97,1.75, body extent -3.5,-2.65 3.5,1.76, height 1.7

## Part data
B1: library part MCD-01335, "Subminiature Side Actuated Tact Switch for SMT - KSS series - 2.0 Newtons - Gull wing, SPST", Manufacturer=C&K, Manufacturer_Part_Number=KSS221GLFS
C1 C7 C12: library part MCD-00012, "Capacitor, MLCC, 2.2uF, 10V, X5R, 10%, 0603, T=0,8mm", Alternate_Manufacturer=KEMET, Alternate_Manufacturer_Part_Number=C0603C225K8PACTU, Manufacturer=YAGEO, Manufacturer_Part_Number=CC0603KRX5R6BB225, Package=C0603
C2 C3 C4 C5 C6 C8 C11 C13 C16 C17 C19 C20 C24 C25 C26 C27 C28 C29 C30 C31 C32 C33 C34 C36 C38 C44 C47: library part MCD-00102, "Capacitor, MLCC, 100nF, 16V, X7R, 10%, 0402, T=0,5mm", Manufacturer=YAGEO, Manufacturer_Part_Number=CC0402KRX7R7BB104, Package=C0402
C9 C15: library part MCD-00009, "Capacitor, MLCC, 4.7uF, 16V, X5R, 10%, 0603, T=0.8mm", Manufacturer=YAGEO, Manufacturer_Part_Number=CC0603KRX5R7BB475, Package=C0603
C10 C18 C35 C39 C40 C43 C45 C46: library part MCD-00010, "Capacitor, MLCC, 1uF, 16V, X5R, 10%, 0603, T=0,8mm", Manufacturer=YAGEO, Manufacturer_Part_Number=CC0603KRX5R7BB105, Package=C0603
C14: library part MCD-00016, "Capacitor, MLCC, 20pF, 50V, NPO, 5%, 0402, T=0,5mm", Manufacturer=YAGEO, Manufacturer_Part_Number=CC0402JRNPO9BN200, Package=C0402
C21 C22: library part MCD-00674, "Capacitor, MLCC, 6.8pF, 50V, NPO, +-0.25pF, 0402, T=0.5mm", Manufacturer=YAGEO, Manufacturer_Part_Number=CC0402CRNPO9BN6R8, Package=C0402
C23: library part MCD-00205, "Capacitor, MLCC, 100pF, 50V, NPO, 5%, 0402, T=0,5mm", Manufacturer=YAGEO, Manufacturer_Part_Number=CC0402JRNPO9BN101, Package=C0402
C37: library part MCD-00011, "Capacitor, MLCC, 10nF, 16V, X7R, 10%, 0402, T=0.5mm", Manufacturer=YAGEO, Manufacturer_Part_Number=CC0402KRX7R7BB103, Package=C0402
C41 C42: library part MCD-00014, "Capacitor, MLCC, 10uF, 25V, X5R, 10%, 0805, T=0,85mm", Manufacturer=YAGEO, Manufacturer_Part_Number=CC0805KRX5R8BB106, Package=C0805
CN1: library part MCD-00028, "USB-MICRO-B, 0.65mm, RA, SMT, Bottom Mount,", Manufacturer=MOLEX, Manufacturer_Part_Number=1050170001
CN2: library part MCD-01430, "SWD connector 2.54pitch 1+3 pins - not fitted", Manufacturer=na
CN3 CN4: library part MCD-01332, "Pin header, 15x1, 2,54mm, VR, TH, Height 6mm/6mm", Manufacturer=LYCN, Manufacturer_Part_Number=313115S161145
D1 D2 D4: library part MCD-00034, "BAT60JFILM", Manufacturer=STMICROELECTRONICS
D3: library part MCD-01059, "LOW DROP POWER SCHOTTKY RECTIFIER 1A 30V VF=0.3V", Manufacturer=STMICROELECTRONICS, Manufacturer_Part_Number=STPS1L30A, Package=DIO_SMA_1A_2K
HW1: library part MCD-00626, "CE logo footprint for PCB"
JP1: library part MCD-01428, "Header, 2x1, 1,27mm, Right Angled, Single Row, Height 3.05mm/1.27mm", Manufacturer="W & P Products", Manufacturer_Part_Number=707-2-02-2-20-00
L1: library part MCD-00047, "SMD Chip ferrite bead, 600R@100MHz +/-25%, 350mA, 500mohm DC, 0603, T=0.8mm", Manufacturer=TAI-TECH, Manufacturer_Part_Number=FCM1608KF-601T03
LD1: library part MCD-00051, "LED Bicolor", Alternate_Manufacturer=EVERLUCK, Alternate_Manufacturer_Part_Number=LE-RGW35280, Manufacturer="AVAGO TECHNOLOGIES", Manufacturer_Part_Number=HSMF-A201-A00J1
LD2 LD4: library part MCD-00050, "LED, Green, 0603", Alternate_Manufacturer="VISHAY SEMICONDUCTOR OPTO DIVISION", Alternate_Manufacturer_Part_Number=VLMTG1300-GS08, Manufacturer="OSRAM OPTO SEMICONDUCTORS", Manufacturer_Part_Number="LG Q396-PS-35", Package="LED 0603"
LD3: library part MCD-00322, "LED, Red, 0603", Alternate_Manufacturer="OSRAM OPTO SEMICONDUCTORS", Alternate_Manufacturer_Part_Number="LS Q976-NR-1", Manufacturer=VISHAY, Manufacturer_Part_Number=VLMS1300-GS08, Package="LED 0603"
Q1: library part MCD-00073, "NPN Bipolar Transistor", Manufacturer=NXP, Manufacturer_Part_Number=BSR14
R1: library part MCD-00055, "Resistor,2K7,0402,1%,1/16W", Manufacturer=YAGEO, Manufacturer_Part_Number=RC0402FR-072K7L, Package=R0402
R2 R3 R20: library part MCD-00065, "Resistor,4K7,0402,1%,1/16W", Alternate_Manufacturer=YAGEO, Alternate_Manufacturer_Part_Number=RT0402FRE074K7L, Manufacturer_Part_Number=RC0402FR-074K7L, Package=R0402
R4 R9 R10 R13 R14 R21: library part MCD-00189, "Resistor,22R,0402,1%,1/16W", Manufacturer=YAGEO, Manufacturer_Part_Number=RC0402FR-0722RL, Package=R0402
R5 R8 R11: library part MCD-00119, "Resistor,100R,0402,1%,1/16W", Manufacturer=YAGEO, Manufacturer_Part_Number=RC0402FR-07100RL, Package=R0402
R6 R12 R22: library part MCD-00053, "Resistor,10K,0402,1%,1/16W", Manufacturer=YAGEO, Manufacturer_Part_Number=RC0402FR-0710KL, Package=R0402
R7: library part MCD-00185, "Resistor,3K,0402,1%,1/16W", Manufacturer=YAGEO, Manufacturer_Part_Number=RC0402FR-073KL, Package=R0402
R15: library part MCD-00220, "Resistor,10K,0603,1%,1/10W", Manufacturer=YAGEO, Manufacturer_Part_Number=RC0603FR-0710KL, Package=R0603
R16: library part MCD-00064, "Resistor,510R,0402,1%,1/16W", Manufacturer=YAGEO, Manufacturer_Part_Number=RC0402FR-07270RL, Package=R0402
R17: library part MCD-00499, "Resistor,620R,0402,1%,1/16W", Manufacturer=YAGEO, Manufacturer_Part_Number=RC0402FR-07620RL, Package=R0402
R18 R19: library part MCD-00197, "Resistor,330R,0603,1%,1/10W", Manufacturer=YAGEO, Manufacturer_Part_Number=RC0603FR-07330RL, Package=R0603
R23: library part MCD-00070, "Resistor,1K,0603,1%,1/10W", Manufacturer=YAGEO, Manufacturer_Part_Number=RC0603FR-071KL, Package=R0603
R24: library part MCD-00059, "Resistor,100K,0402,1%,1/16W", Alternate_Manufacturer=YAGEO, Alternate_Manufacturer_Part_Number=RT0402FRE07100KL, Manufacturer_Part_Number=RC0402FR-07100KL, Package=R0402
R25: library part MCD-00063, "Resistor,47K,0402,1%,1/16W", Manufacturer=YAGEO, Manufacturer_Part_Number=RC0402FR-0747KL, Package=R0402
SB1 SB2 SB3 SB4 SB5 SB6 SB7 SB8 SB9 SB10 SB11 SB12 SB13 SB14 SB15 SB16: library part MCD-00071, "Solder Bridge ON", Manufacturer=YAGEO, Manufacturer_Part_Number=RC0603JR-070RL, Package=SB0603
U1: library part MCD-01396, "STM32G431, LQFP32 package, with double footprint (LQFP32_5V & UFQFPN32_A0B8)", Manufacturer=STMICROELECTRONICS, Manufacturer_Part_Number=STM32G431KBT6, Package=LQFP32-5V
U2: library part MCD-00170, "ESD protection 6V1", Manufacturer=STMICROELECTRONICS, Manufacturer_Part_Number=ESDALC6V1-1U2
U3: library part MCD-00251, "High power transient voltage suppressor, 7V breakdown", Manufacturer=STMICROELECTRONICS, Manufacturer_Part_Number=ESDA7P60-1U1M
U4: library part MCD-00649, "Common mode filter with ESD protection for USB 2.0 interface", Manufacturer=STMICROELECTRONICS, Manufacturer_Part_Number=ECMF02-2AMX6
U5: library part MCD-00596, "STM32F723IEK  (STM32F7) BGA176", Manufacturer=STMICROELECTRONICS, Manufacturer_Part_Number=STM32F723IEK6
U6: library part MCD-00086, "Ultra low drop-low noise BiCMOS voltage, regulators low ESR capacitors compatible", Manufacturer=STMICROELECTRONICS, Manufacturer_Part_Number=LD3985M33R
U7: library part MCD-00159, "500mA, Enhanced single channel power switches with active high enable pin", Alternate_Manufacturer="TEXAS INSTRUMENTS", Alternate_Manufacturer_Part_Number=TPS2051C, Manufacturer=STMICROELECTRONICS, Manufacturer_Part_Number=STMPS2151STR
U8: library part MCD-00088, "IC REG LDO 5V 0.8A SOT223", Manufacturer=STMICROELECTRONICS, Manufacturer_Part_Number=LD1117S50TR, Package=SOT-223
U9: library part MCD-00215, "Low quiescent current and low noise voltage regulators", Manufacturer=STMICROELECTRONICS, Manufacturer_Part_Number=LD39050PU33R, Package="DFN6 3x3mm"
X1: library part MCD-00597, "Oscillator 25.00Mhz, -+50PPM, 3.3V, Temp -55 to +125°C", Alternate_Manufacturer="AVX CORP/KYOCERA CORP", Alternate_Manufacturer_Part_Number=KC2520B25.0000C10E00, Manufacturer=NDK, Manufacturer_Part_Number="NZ2520SB 25MHz END4869B"
X2: library part MCD-01036, "24MHz crystal oscillator - Cl:6pf -", Manufacturer=NDK, Manufacturer_Part_Number="NX2016SA 24MHz EXS00A-CS10820", Package="(2016) 2.0 x 1.6 x 0.45 mm"

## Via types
v1: diameter 0.45, hole 0.2, Top Layer to Bottom Layer, tented both sides, 241 vias

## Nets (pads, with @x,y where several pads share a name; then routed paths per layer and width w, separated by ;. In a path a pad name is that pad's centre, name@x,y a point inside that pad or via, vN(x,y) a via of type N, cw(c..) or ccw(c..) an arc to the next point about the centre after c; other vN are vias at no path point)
3V3: CN3.14 JP1.1 R3.2 R16.2 SB15.2 | length 55.7
  Top Layer w0.3: v1(3.5,41.3) 4.525,41.3 5.05,41.825 R3.2@5.05,41.925 ; v1(13.525,4.6) 13.5,4.575 13.5,4.625 13.9,5.025 R16.2@13.9,5.525 14.25,5.525 SB15.2@15.2,6.475 16.891,8.166 CN3.14@16.891,8.382
  Signal Layer 2 w0.3: v1(3.3,30.825) 4.15,31.675 4.15,31.925 4.425,32.2 4.425,32.975 5.05,33.6 5.05,40.625 4.375,41.3 v1(3.5,41.3)
  Signal Layer 2 w0.4: JP1.1@5.265,5.45 6.575,5.45 7.28,4.745 13.38,4.745 v1(13.525,4.6)
  Bottom Layer w0.3: v1(3.3,30.825) 2.926,30.451 2.926,18.045 3.331,17.64 4.11,17.64 4.35,17.4 4.35,12.314 5.57,11.094 5.57,6.825 5.265,6.52 JP1.1@5.265,5.45 JP1.1@5.115,5.6
3V3_STLK: C2.2 C3.2 C4.2 C5.2 C6.2 C8.2 C9.2 C10.2 C13.2 C24.2 C25.2 C26.2 C27.2 C28.2 C29.2 C30.2 C31.2 C32.2 C33.2 C34.2 C35.2 C36.2 CN2.1 LD1.4 R12.1 U5.C1 U5.C5 U5.C6 U5.C7 U5.C8 U5.C9 U5.F3 U5.G3 U5.G13 U5.H13 U5.J12 U5.J13 U5.K4 U5.N8 U5.N9 U5.N10 U5.P1 U5.R1 U6.5 X1.4 | length 165.1
  Top Layer w0.25: v1(7.2,40.075) C4.2@7.2,40.9
  Top Layer w0.3: C13.2@3.25,35.7 3.25,36.125 v1(3.5,36.375) 3.55,36.425 X1.4@4.425,36.425 ; v1(7.3,38) C8.2@8.05,38 ; v1(9,36.3) 9,37.25 C9.2@9.175,37.425 ; v1(9.475,40.125) C2.2@9.475,40.8 ; v1(9.675,36.275) 10,36.275 10.525,36.8 C10.2@10.525,37.425 ; C3.2@10.375,40.8 10.375,39.794 v1(10.399,39.77) ; v1(11.475,38.325) 11.725,38.325 12.55,39.15 C6.2@12.675,39.15 ; v1(11.475,39.004) 11.504,39.004 12.5,40 C5.2@12.65,40 ; 15.47,42.105 15.47,40.255 15.625,40.1 15.625,39.399 15.616,39.39 15.616,38.209 v1(15.675,38.15) 15.675,37.559 15.616,37.5 15.616,35.302
  Top Layer w0.45: LD1.4@1.155,48.363 1.155,47.97 1.975,47.15 v1(3.8,47.15) 3.8,45.031 3.705,44.936 3.705,44.17 ; v1(3.475,42.8) 3.475,43.94 3.705,44.17 ; v1(4.5,43.775) 4.1,43.775 3.705,44.17
  Top Layer w0.5: R12.1@3.525,33.85 3.525,32.675 v1(3.775,32.425) 3.975,32.225 v1(5.4,32.225) v1(6.8,32.225) v1(8.2,32.225) v1(10.65,32.225) v1(12.05,32.225) v1(13.45,32.225) 14.3,31.375 15.15,31.375 ; v1(10.45,27.825) 11.25,27.825 ; v1(11.9,27.175) 11.25,27.825 ; CN2.1@14.351,46.482 14.351,45.074 15.47,43.955 15.47,42.105 ; 15.616,35.302 15.5,35.186 15.252,35.186 15.246,35.18 14.978,35.18 14.7,34.902 14.7,34.867 14.656,34.823 14.656,34.33 15.475,33.511 15.475,31.7 15.15,31.375 ; 11.25,27.825 11.85,28.425 v1(12.2,28.425) 14.075,28.425 14.97,29.32 14.97,31.195 15.15,31.375
  Signal Layer 2 w0.3: 2.825,38.125 2.926,38.226 2.926,39.726 2.945,39.745 2.945,40.385 3.33,40.77 ; v1(3.475,42.8) 2.926,42.251 2.926,41.174 3.33,40.77 ; 3.775,36.1 4.595,36.92 4.595,40.18 4.005,40.77 3.33,40.77 ; v1(10.45,27.825) 9.575,28.7 9.575,29.25 10.65,30.325 v1(10.65,32.225)
  Signal Layer 2 w0.4: v1(6.925,43.775) 6.956,43.744 6.956,42.444 ; v1(9,36.3) 9.65,36.3 v1(9.675,36.275) ; v1(9.475,40.125) 10.044,40.125 v1(10.399,39.77) ; v1(15.675,37.5) v1(15.675,38.15)
  Signal Layer 2 w0.45: v1(11.9,27.175) 11.9,28.125 v1(12.2,28.425)
  Signal Layer 2 w0.5: v1(3.5,36.375) 3.775,36.1 v1(3.775,32.425) ; 6.956,42.444 7.2,42.2 v1(7.2,40.075) 6.725,39.6 6.725,38.25 6.975,38 ; v1(7.3,38) 6.975,38 ; v1(8.2,32.225) v1(6.8,32.225) 6.73,32.295 6.73,37.755 6.975,38 ; v1(9.475,40.125) 9.475,38.75 9.675,38.55 v1(9.675,36.275) 9.655,36.255 9.655,33.22 v1(10.65,32.225) ; v1(11.475,39.004) v1(11.475,38.325) 11.881,38.325 12.175,38.031 12.175,32.35 v1(12.05,32.225)
  Bottom Layer w0.16: v1(3.5,36.375) 5.696,36.375 U5.F3@6.021,36.7 ; U5.G3@6.021,37.35 6.346,37.675 6.975,37.675 v1(7.3,38) ; 6.346,33.096 6.346,34.25 6.521,34.425 6.996,34.425 U5.C5@7.321,34.75 ; 7.646,33.129 7.646,34.425 U5.C6@7.971,34.75 ; U5.C7@8.621,34.75 8.946,34.425 8.946,33.154 9.15,32.95 9.275,32.95 ; 8.65,43 8.946,42.704 8.946,41.575 U5.N8@9.271,41.25 ; U5.C8@9.271,34.75 9.596,34.425 9.596,33.315 9.981,32.931 ; v1(9.475,40.125) 9.596,40.246 9.596,40.379 ; 9.6,40.375 9.596,40.379 ; U5.C9@9.921,34.75 10.246,34.425 10.246,33.886 10.357,33.775 11.356,33.775 11.546,33.585 11.546,33.129 11.625,33.05 ; U5.N9@9.921,41.25 9.921,41.053 9.915,41.053 9.596,40.735 9.596,40.379 ; v1(10.399,39.77) v1(10.399,39.77) 10.4,39.775 10.246,39.929 10.246,40.925 U5.N10@10.571,41.25 ; v1(11.475,38.325) 12.196,38.325 U5.J13@12.521,38.65 ; v1(11.475,39.004) 11.496,39.025 U5.J12@11.871,38.65 ; U5.G13@12.521,37.35 12.846,37.675 14.2,37.675 ; U5.H13@12.521,38 12.846,38.325 14.1,38.325 14.225,38.325
  Bottom Layer w0.25: C26.2@3.475,43.475 4,43.475 4.2,43.275 4.2,42.175 4.475,41.9 U5.P1@4.721,41.9 ; U5.R1@4.721,42.55 4.721,42.821 5.175,43.275 C25.2@5.175,43.775 ; U5.K4@6.671,39.3 7.2,39.829 v1(7.2,40.075)
  Bottom Layer w0.3: v1(3.475,42.8) C26.2@3.475,43.475 ; v1(4.5,43.775) C25.2@5.175,43.775 ; U5.C1@4.721,34.75 4.3,34.329 4.3,33.25 4.725,32.825 C34.2@4.725,32.225 v1(5.4,32.225) ; 6.346,33.096 6.125,32.875 C33.2@6.125,32.225 v1(6.8,32.225) ; v1(6.925,43.775) C24.2@7.575,43.775 7.875,43.775 8.65,43 ; 7.646,33.129 7.55,33.033 7.55,32.25 C32.2@7.525,32.225 v1(8.2,32.225) ; 9.275,32.95 9.975,32.25 C31.2@9.975,32.225 v1(10.65,32.225) ; 9.981,32.925 11.025,32.925 11.375,32.575 C30.2@11.375,32.225 v1(12.05,32.225) ; v1(10.45,27.825) C35.2@10.45,28.5 ; U6.5@11.225,27.175 v1(11.9,27.175) ; C36.2@11.55,28.425 v1(12.2,28.425) ; 11.625,33.05 11.8,32.875 12.575,32.875 12.775,32.675 C29.2@12.775,32.225 v1(13.45,32.225) ; 14.2,37.675 14.525,37.35 C28.2@15,37.35 15.525,37.35 v1(15.675,37.5) ; 14.225,38.325 14.4,38.15 C27.2@15,38.15 v1(15.675,38.15)
5V: C46.2 C47.2 CN3.4 D3.2 D4.2 R1.2 R17.2 U9.1 U9.6 | length 89.5
  Top Layer w0.3: R1.2@6.15,44.675 6.675,44.675 v1(6.925,44.425)
  Top Layer w0.4: v1(6.85,29.925) 6.895,29.88 11.305,29.88 11.425,30
  Top Layer w0.45: R17.2@15.725,1.7 16.7,1.7 ; 16.7,1.7 16.95,1.95 16.95,2.5 v1(17.225,2.775) v1(17.225,2.275) v1(17.225,1.7) 16.7,1.7
  Top Layer w0.5: 11.425,30 v1(13.15,30) v1(13.7,30.55)
  Signal Layer 2 w0.4: v1(6.85,29.925) 6.85,31.125 6.1,31.875 6.1,41.575 5.05,42.625 5.05,43.45 5.92,44.32 6.82,44.32 v1(6.925,44.425)
  Signal Layer 2 w0.45: 16.15,2.075 16.35,2.275
  Signal Layer 2 w0.6: v1(13.7,30.55) v1(13.15,30) 13.13,29.98 13.13,28.08 12.73,27.68 12.73,22.595 13.1,22.225 13.1,15.121 13.99,14.231 13.99,10.348 14.656,9.682 14.656,8.668 14.08,8.092 14.08,5.867 16.15,3.797 16.15,3.45 ; 16.35,2.275 v1(17.225,2.275) ; 16.15,2.75 16.175,2.775 16.825,2.775 ; 16.15,2.75 16.15,2.075 16.525,1.7 v1(17.225,1.7) v1(17.225,2.275) ; 16.15,2.75 16.15,3.45 ; 16.15,3.45 16.825,2.775 ; 16.825,2.775 v1(17.225,2.775) v1(17.225,2.275)
  Bottom Layer w0.45: D3.2@10.025,2.76 11.04,2.76 11.325,2.475 11.325,1.975 ; C47.2@11.325,1.4 11.325,1.975 ; 12.125,1.27 12.225,1.37 U9.1@12.225,2 11.35,2 11.325,1.975 ; 12.475,1.27 12.5,1.295 ; 14.825,1.27 U9.6@14.825,2 16.284,2 C46.2@16.292,2.008 ; 16.275,1.27 16.292,1.287 C46.2@16.292,2.008 ; v1@17.225,1.475 C46.2@16.692,2.008 ; v1(17.225,2.275) 16.958,2.008 C46.2@16.692,2.008 ; C46.2@16.292,2.008 C46.2@16.692,2.008
  Bottom Layer w0.6: D4.2@7.375,2.805 9.98,2.805 D3.2@10.025,2.76 ; C47.2@11.325,1.4 11.455,1.27 12.125,1.27 12.475,1.27 14.825,1.27 16.275,1.27 17.02,1.27 17.225,1.475 v1(17.225,1.7) v1(17.225,2.275) v1(17.225,2.775) ; v1(13.15,30) v1(13.7,30.55) 14.3,31.15 15.141,31.15 15.466,31.475 15.466,31.941 16.891,33.366 CN3.4@16.891,33.782
5V_USB_CHGR: C23.2 C39.2 CN1.1 D1.1 R23.1 U3.1 U7.5 | length 49.3
  Top Layer w0.25: CN1.1@10.571,46.142 10.571,46.571 11.35,47.35 v1(12,47.35)
  Signal Layer 2 w0.3: 5.22,31.48 4.905,31.795 4.905,32.63 5.55,33.275 5.55,41.25 4.35,42.45 4.35,42.925 3.55,43.725 3.55,44.8 4.725,45.975 4.725,46.6 5.625,47.5 v1(7.275,47.5)
  Signal Layer 2 w0.5: v1(3.825,29.5) 4.225,29.9 4.975,29.9 5.425,30.35 5.425,31.275 5.22,31.48
  Bottom Layer w0.25: v1(7.275,47.5) U3.1@7.275,48.375 7.775,48.875 8.35,48.875 C23.2@8.475,48.75 8.6,48.875 10.925,48.875 12,47.8 v1(12,47.35)
  Bottom Layer w0.5: v1(3.825,29.5) 3.825,23.85 ; R23.1@4.075,19.95 4.025,20 4.025,21.05 3.825,21.25 3.825,23.85 ; U7.5@7.525,20.8 U7.5@7.525,21.125 ; D1.1@9.08,20.925 7.725,20.925 U7.5@7.525,21.125 ; 3.825,23.85 5.9,23.85 6.475,23.275 7,23.275 7.475,22.8 C39.2@7.475,22.65 7.525,22.6 U7.5@7.525,21.125
5V_USB_STLK: C43.2 D4.1 U7.1 | length 14.8
  Bottom Layer w0.45: 6.68,15.425 6.68,15.624 6.695,15.64 6.695,16.72 6.737,16.762
  Bottom Layer w0.5: 6.68,15.425 6.4,15.145 6.4,13.625 7.05,12.975 7.05,7.4 7.375,7.075 D4.1@7.375,4.945 ; 6.737,16.762 C43.2@7.3,17.325 7.35,17.375 7.35,17.875 7.525,18.05 U7.1@7.525,18.925
5V_VIN: C42.2 D2.1 D3.1 U8.2 U8.4 | length 12.7
  Bottom Layer w0.5: D2.1@9.08,19.025 10.075,18.03 C42.2@10.075,17.1
  Bottom Layer w1: D3.1@10.025,6.79 10.1,6.865 U8.4@10.1,8.825 U8.2@10.1,15.175 10.1,17.075 C42.2@10.075,17.1
AGND: C17.1 C18.1 SB16.2 U1.14 | length 11.2
  Top Layer w0.2: C18.1@15,16.175 15,16.484 15.665,17.149 15.665,19.56 C17.1@15.625,19.6
  Top Layer w0.3: U1.14@11.696,15.719 12.294,15.719 12.744,16.169 U1.14@13.521,16.169 14.994,16.169 C18.1@15,16.175 15,15.726 v1(15.301,15.426)
  Bottom Layer w0.3: SB16.2@14.525,12.875 14.38,13.02 14.38,14.08 14.67,14.37 14.92,14.37 15.301,14.751 v1(15.301,15.426)
ARD_A2: CN3.10 SB14.1 | length 14.8
  Top Layer w0.12: SB14.1@13.625,6.75 13.775,6.75 14.725,7.7 v1(14.725,7.825)
  Bottom Layer w0.12: v1(14.725,7.825) 14.725,7.892 16.4,9.567 17.467,9.567 18.082,10.182 18.082,17.351 CN3.10@16.891,18.542
AVDD: C17.2 C18.2 CN3.13 L1.1 SB5.1 U1.15 | length 21.3
  Top Layer w0.3: U1.15@11.696,16.219 12.019,16.219 12.769,16.969 U1.15@13.521,16.969 14.394,16.969 C18.2@15,17.575 15,18.125 v1(14.7,18.425) 14.725,18.45 C17.2@14.725,19.6 15.1,19.975 15.1,20.525 L1.1@15.25,20.675 13.9,20.675 13.9,20.825 SB5.1@13.8,20.925
  Bottom Layer w0.3: v1(14.7,18.425) 14.7,18.4 14.896,18.204 14.896,16.4 14.491,15.995 14.27,15.995 13.96,15.685 13.96,13.885 13.6,13.525 13.6,10.85 14.5,9.95 15.919,9.95 CN3.13@16.891,10.922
